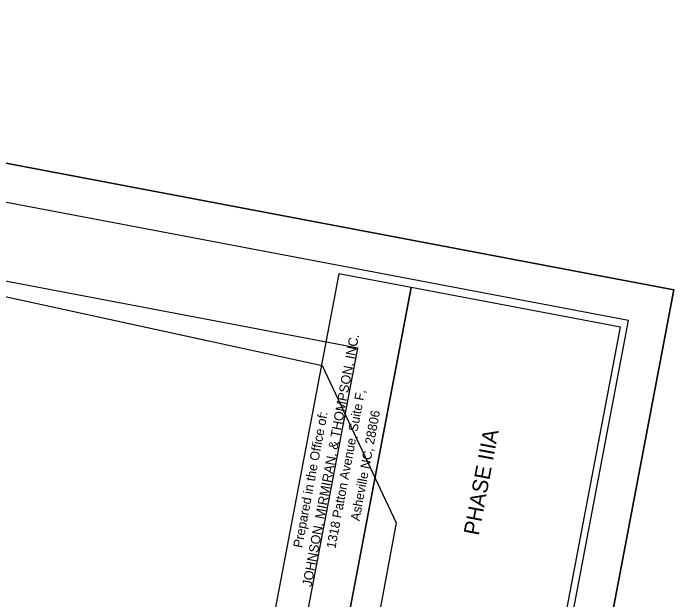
# Model space of a CAD drawing. Extents: x 1615680 to 1619687, y 899305 to 902270.
# Drawn here: x 1616649.2 to 1617075.3, y 900763.2 to 901141.7 of the extents above; entities that cross this region are included whole.
import ezdxf

# ---------------------------------------------------------------- set-up
doc = ezdxf.new("R2010")
doc.units = 0
for name, color, linetype in [('DEV PSS CELL', 7, 'Continuous'), ('PCB (Plan View)', 7, 'Continuous'), ('Prop Conc 4in Sidewalk', 7, 'Continuous'), ('Prop Lane Arrow CELL', 7, 'Continuous'), ('Scratch_Level_7', 7, 'Continuous'), ('Scratch_Level_8', 7, 'Continuous'), ('Stage 5', 7, 'Continuous'), ('Stage 6', 7, 'Continuous')]:
    doc.layers.add(name, color=color, linetype=linetype)

msp = doc.modelspace()

# ---------------------------------------------------------------- linework, layer by layer
at = {"layer": 'DEV PSS CELL'}
msp.add_lwpolyline([(1616859.19, 900973.59), (1616804.79, 900687.04), (1616851.47, 900678.18), (1616905.88, 900964.73)], close=True, dxfattribs=at)
at = {"layer": 'Prop Conc 4in Sidewalk'}
msp.add_lwpolyline([(1616176.29, 901060.7), (1616848.46, 900914.27), (1616896.28, 900812.91), (1616872.94, 900688.21), (1616835.87, 900695.21), (1616753.94, 900262.18), (1616898.09, 900233.43), (1616734.79, 899562.1), (1616202.98, 899609.43), (1616198.71, 899647.14), (1615822.69, 899825.07), (1616054.34, 901080.76)], close=True, dxfattribs=at)
at = {"layer": 'Prop Lane Arrow CELL'}
msp.add_line((1616176.29, 901060.7), (1616775.18, 900930.23), dxfattribs=at)
at = {"layer": 'Scratch_Level_7'}
for points in [[(1616014.55, 901139.21), (1615734.74, 899665.53), (1616766.32, 899469.67), (1617046.12, 900943.35)], [(1616905.88, 900964.73), (1616861.86, 900732.87), (1616996.95, 900707.23), (1617040.97, 900939.08)]]:
    msp.add_lwpolyline(points, close=True, dxfattribs=at)
at = {"layer": 'Scratch_Level_8'}
msp.add_lwpolyline([(1616054.34, 901080.76), (1615793.19, 899705.33), (1616726.52, 899528.12), (1616890.46, 900391.55), (1616774.26, 900413.61), (1616871.48, 900925.61)], close=True, dxfattribs=at)
at = {"layer": 'Stage 5'}
for points in [[(1616760.47, 899304.87), (1615679.78, 899510.06), (1615994.65, 901168.43), (1617075.34, 900963.24)], [(1616760.47, 899304.87), (1617075.34, 900963.24), (1615994.65, 901168.43), (1615679.78, 899510.06)]]:
    msp.add_lwpolyline(points, close=True, dxfattribs=at)

# ---------------------------------------------------------------- texts
at = {"layer": 'PCB (Plan View)'}
for s, height, p in [('JOHNSON, MIRMIRAN, & THOMPSON, INC.', 6.0929, (1616841.6, 900771.3)), ('1318 Patton Avenue, Suite F,', 5.9679, (1616857.01, 900795.9)), ('Prepared in the Office of:', 5.9987, (1616835.57, 900796.39)), ('Asheville NC, 28806', 5.9679, (1616872.53, 900813.77))]:
    msp.add_text(s, height=height, rotation=79.301, dxfattribs=at).set_placement(p)
at = {"layer": 'Stage 6'}
msp.add_text('PHASE IIIA', height=10, rotation=79.2494, dxfattribs=at).set_placement((1616949.51, 900804.28))

doc.saveas('drawing.dxf')
